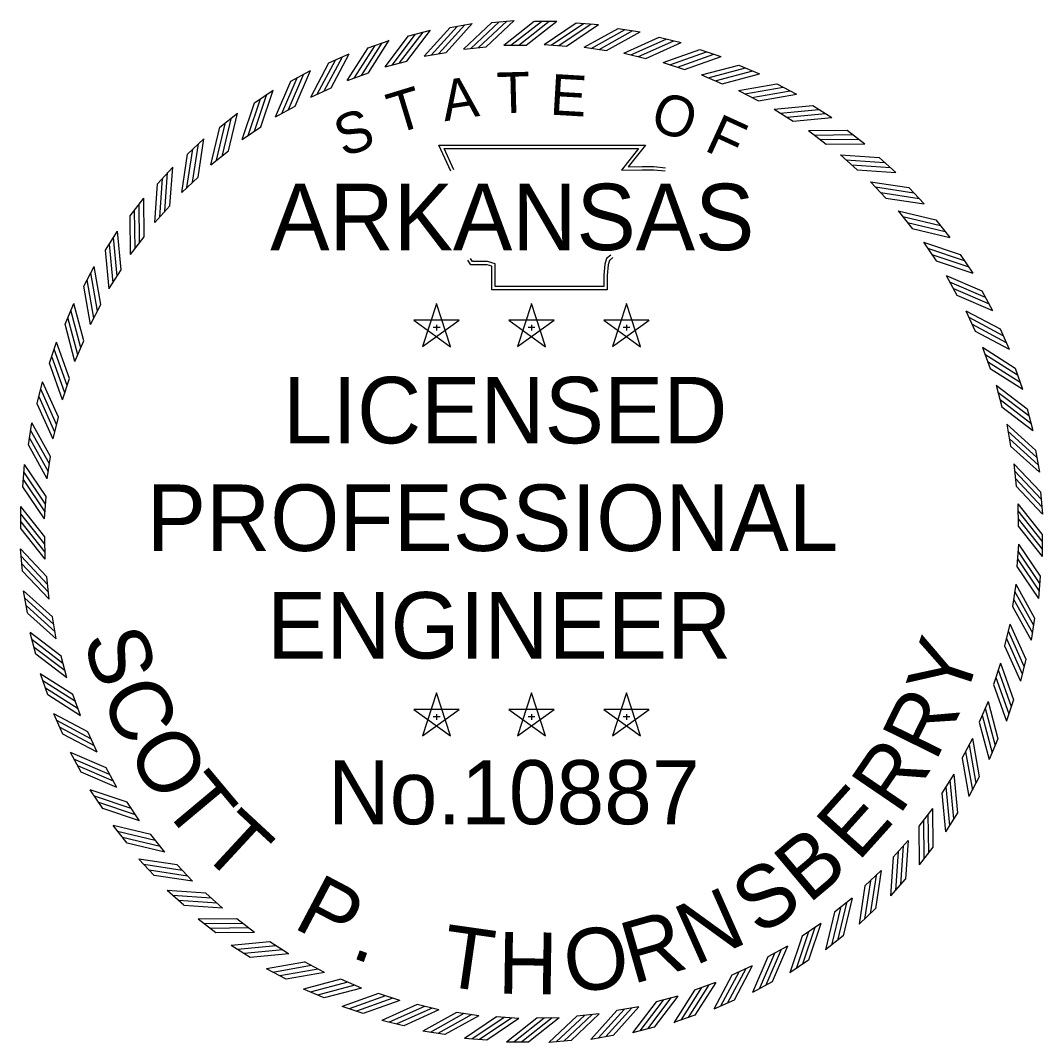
# Model space of a CAD drawing. Extents: x 185 to 5012, y 113 to 2127.
# Drawn here: x 2962.6 to 3211.1, y 185.8 to 434.2 of the extents above; entities that cross this region are included whole.
import ezdxf

# ---------------------------------------------------------------- set-up
doc = ezdxf.new("R2010")
doc.units = 0
doc.layers.add('STAMP_PP', color=7, linetype='Continuous')

msp = doc.modelspace()

# ---------------------------------------------------------------- linework, layer by layer
at = {"layer": 'STAMP_PP'}
for p, q in [((3067.05, 432.52), (3072.41, 433.46)), ((3077.23, 433.74), (3082.65, 434.24)), ((3087.54, 434.04), (3092.98, 434.04)), ((3097.73, 433.63), (3103.15, 433.23)), ((3107.9, 432.31), (3113.27, 431.47)), ((3057, 430.47), (3062.26, 431.85)), ((3117.92, 430.16), (3123.21, 428.87)), ((3047.16, 427.59), (3052.29, 429.4)), ((3070.37, 427.29), (3075.8, 427.79)), ((3080.11, 428.25), (3085.56, 428.25)), ((3089.9, 428.4), (3095.34, 428)), ((3099.66, 427.75), (3105.05, 426.9)), ((3037.58, 423.91), (3042.55, 426.14)), ((3060.74, 425.53), (3066.11, 426.48)), ((3109.34, 426.29), (3114.64, 425)), ((3127.74, 427.18), (3132.9, 425.46)), ((3051.29, 422.98), (3056.57, 424.37)), ((3118.87, 424.03), (3124.04, 422.31)), ((3137.27, 423.4), (3142.28, 421.26)), ((3028.35, 419.45), (3033.11, 422.09)), ((3042.09, 419.66), (3047.23, 421.47)), ((3128.17, 421), (3133.18, 418.85)), ((3033.19, 415.59), (3038.16, 417.82)), ((3146.46, 418.85), (3151.27, 416.31)), ((3019.51, 414.25), (3024.04, 417.27)), ((3137.19, 417.21), (3142.01, 414.66)), ((3024.65, 410.79), (3029.42, 413.43)), ((3145.87, 412.68), (3150.47, 409.74)), ((3155.25, 413.56), (3159.83, 410.62)), ((3011.13, 408.33), (3015.4, 411.71)), ((3016.54, 405.31), (3021.08, 408.34)), ((3154.15, 407.46), (3158.48, 404.15)), ((3163.56, 407.55), (3167.89, 404.25)), ((3003.27, 401.74), (3007.24, 405.46)), ((3008.91, 399.18), (3013.19, 402.57)), ((3161.97, 401.57), (3166.01, 397.91)), ((3171.36, 400.89), (3175.39, 397.24)), ((2995.98, 394.53), (2999.63, 398.56)), ((3001.82, 392.44), (3005.79, 396.17)), ((3169.27, 395.05), (3173, 391.07)), ((3178.57, 393.6), (3182.29, 389.63)), ((2989.32, 386.74), (2992.62, 391.06)), ((2995.3, 385.14), (2998.96, 389.18)), ((3176.01, 387.96), (3179.4, 383.68)), ((3185.16, 385.74), (3188.54, 381.47)), ((2983.31, 378.42), (2986.25, 383)), ((2989.41, 377.32), (2992.72, 381.66)), ((3182.14, 380.33), (3185.17, 375.79)), ((3191.08, 377.36), (3194.09, 372.83)), ((2978.02, 369.64), (2980.56, 374.44)), ((2984.19, 369.05), (2987.13, 373.64)), ((3187.62, 372.22), (3190.26, 367.45)), ((3196.28, 368.52), (3198.92, 363.76)), ((2973.47, 360.45), (2975.61, 365.45)), ((3063.76, 365.39), (3060.36, 354.95)), ((3067.15, 354.96), (3063.77, 365.4)), ((3086.84, 365.39), (3083.43, 354.95)), ((3090.23, 354.96), (3086.85, 365.4)), ((3109.92, 365.39), (3106.51, 354.95)), ((3113.31, 354.96), (3109.92, 365.4)), ((2979.66, 360.37), (2982.21, 365.19)), ((3192.41, 363.68), (3194.65, 358.71)), ((3069.25, 361.41), (3058.26, 361.42)), ((3058.27, 361.41), (3067.15, 354.94)), ((3060.37, 354.96), (3069.26, 361.4)), ((3063.77, 360.24), (3063.77, 358.86)), ((3092.33, 361.41), (3081.34, 361.42)), ((3081.35, 361.41), (3090.23, 354.94)), ((3083.45, 354.96), (3092.34, 361.4)), ((3086.85, 360.24), (3086.85, 358.86)), ((3115.4, 361.41), (3104.42, 361.42)), ((3104.43, 361.41), (3113.31, 354.94)), ((3106.53, 354.96), (3115.42, 361.4)), ((3109.93, 360.24), (3109.93, 358.86)), ((3062.98, 359.65), (3064.61, 359.65)), ((3086.06, 359.65), (3087.69, 359.65)), ((3109.13, 359.65), (3110.77, 359.65)), ((3200.74, 359.29), (3202.97, 354.32)), ((2969.69, 350.91), (2971.41, 356.07)), ((2975.87, 351.34), (2978.02, 356.36)), ((3196.48, 354.78), (3198.3, 349.64)), ((3204.42, 349.71), (3206.23, 344.58)), ((2966.71, 341.1), (2968, 346.38)), ((2972.84, 342.04), (2974.56, 347.21)), ((3199.81, 345.58), (3201.19, 340.3)), ((3207.29, 339.87), (3208.68, 334.61)), ((2964.56, 331.07), (2965.4, 336.44)), ((2970.58, 332.51), (2971.87, 337.81)), ((3202.36, 336.13), (3203.3, 330.76)), ((2969.12, 322.83), (2969.97, 328.22)), ((3209.35, 329.82), (3210.29, 324.46)), ((2963.24, 320.9), (2963.64, 326.32)), ((3204.12, 326.5), (3204.62, 321.07)), ((2968.47, 313.07), (2968.87, 318.51)), ((3210.56, 319.64), (3211.06, 314.22)), ((2962.76, 310.65), (2962.71, 316.09)), ((3205.08, 316.76), (3205.13, 311.31)), ((2968.62, 303.28), (2968.57, 308.74)), ((3210.94, 309.39), (3210.99, 303.95)), ((2963.13, 300.4), (2962.63, 305.82)), ((3205.23, 306.97), (3204.83, 301.53)), ((2969.58, 293.54), (2969.08, 298.97)), ((3210.46, 299.14), (3210.06, 293.72)), ((3204.57, 297.21), (3203.73, 291.82)), ((2964.35, 290.22), (2963.4, 295.58)), ((2971.34, 283.91), (2970.39, 289.29)), ((3209.14, 288.97), (3208.29, 283.6)), ((3203.11, 287.53), (3201.82, 282.23)), ((2966.4, 280.17), (2965.02, 285.43)), ((2973.89, 274.47), (2972.5, 279.74)), ((3206.98, 278.95), (3205.7, 273.66)), ((3200.86, 278), (3199.14, 272.83)), ((2969.28, 270.33), (2967.47, 275.46)), ((2977.21, 265.26), (2975.39, 270.4)), ((3063.76, 270.77), (3060.36, 260.33)), ((3067.15, 260.33), (3063.77, 270.78)), ((3086.84, 270.77), (3083.43, 260.33)), ((3090.23, 260.33), (3086.85, 270.78)), ((3109.92, 270.77), (3106.51, 260.33)), ((3113.31, 260.33), (3109.92, 270.78)), ((3197.83, 268.7), (3195.68, 263.68)), ((3204.01, 269.13), (3202.29, 263.97)), ((3069.25, 266.78), (3058.26, 266.79)), ((3058.27, 266.78), (3067.15, 260.32)), ((3060.37, 260.33), (3069.26, 266.78)), ((3092.33, 266.78), (3081.34, 266.79)), ((3081.35, 266.78), (3090.23, 260.32)), ((3083.45, 260.33), (3092.34, 266.78)), ((3115.4, 266.78), (3104.42, 266.79)), ((3104.43, 266.78), (3113.31, 260.32)), ((3106.53, 260.33), (3115.42, 266.78)), ((2972.96, 260.76), (2970.73, 265.72)), ((3062.98, 265.03), (3064.61, 265.03)), ((3063.77, 265.61), (3063.77, 264.24)), ((3086.06, 265.03), (3087.69, 265.03)), ((3086.85, 265.61), (3086.85, 264.24)), ((3109.13, 265.03), (3110.77, 265.03)), ((3109.93, 265.61), (3109.93, 264.24)), ((2981.28, 256.36), (2979.05, 261.33)), ((3194.04, 259.68), (3191.48, 254.86)), ((3200.23, 259.6), (3198.09, 254.59)), ((2977.42, 251.52), (2974.78, 256.28)), ((2986.08, 247.82), (2983.44, 252.6)), ((3189.51, 251), (3186.57, 246.4)), ((3195.68, 250.4), (3193.13, 245.6)), ((2982.62, 242.68), (2979.6, 247.21)), ((2991.56, 239.71), (2988.53, 244.25)), ((3184.29, 242.72), (3180.98, 238.39)), ((3190.38, 241.62), (3187.45, 237.04)), ((2988.54, 234.3), (2985.16, 238.57)), ((2997.69, 232.09), (2994.3, 236.36)), ((3178.4, 234.9), (3174.74, 230.86)), ((3184.38, 233.3), (3181.08, 228.98)), ((2995.13, 226.44), (2991.4, 230.41)), ((3004.43, 224.99), (3000.7, 228.97)), ((3171.88, 227.6), (3167.9, 223.87)), ((3177.71, 225.51), (3174.07, 221.48)), ((3002.34, 219.16), (2998.3, 222.8)), ((3011.73, 218.47), (3007.69, 222.13)), ((3164.78, 220.86), (3160.51, 217.47)), ((3170.42, 218.3), (3166.46, 214.58)), ((3010.13, 212.49), (3005.81, 215.79)), ((3019.55, 212.58), (3015.21, 215.89)), ((3157.15, 214.73), (3152.62, 211.7)), ((3162.57, 211.71), (3158.3, 208.33)), ((3018.45, 206.49), (3013.87, 209.42)), ((3027.82, 207.36), (3023.23, 210.3)), ((3149.05, 209.25), (3144.27, 206.61)), ((3027.23, 201.19), (3022.42, 203.74)), ((3036.5, 202.83), (3031.68, 205.39)), ((3140.51, 204.46), (3135.54, 202.22)), ((3154.19, 205.79), (3149.66, 202.77)), ((3036.42, 196.64), (3031.42, 198.78)), ((3045.53, 199.04), (3040.51, 201.19)), ((3131.61, 200.38), (3126.47, 198.57)), ((3145.35, 200.59), (3140.59, 197.95)), ((3054.83, 196.01), (3049.66, 197.73)), ((3122.4, 197.06), (3117.13, 195.68)), ((3045.96, 192.86), (3040.8, 194.58)), ((3064.36, 193.75), (3059.06, 195.04)), ((3112.95, 194.51), (3107.58, 193.57)), ((3136.11, 196.13), (3131.15, 193.9)), ((3074.03, 192.29), (3068.65, 193.14)), ((3083.8, 191.64), (3078.36, 192.04)), ((3093.59, 191.79), (3088.13, 191.74)), ((3103.33, 192.75), (3097.9, 192.25)), ((3126.54, 192.45), (3121.41, 190.64)), ((3055.77, 189.89), (3050.49, 191.17)), ((3116.7, 189.57), (3111.43, 188.19)), ((3065.8, 187.73), (3060.43, 188.58)), ((3075.97, 186.41), (3070.54, 186.81)), ((3106.65, 187.52), (3101.29, 186.58)), ((3086.22, 185.93), (3080.78, 185.88)), ((3096.46, 186.3), (3091.05, 185.81))]:
    msp.add_line(p, q, dxfattribs=at)
for points in [[(3060.74, 425.52), (3067.04, 432.51)], [(3062.46, 425.81), (3068.77, 432.8)], [(3064.32, 426.18), (3070.62, 433.17)], [(3066.11, 426.48), (3072.41, 433.47)], [(3070.36, 427.28), (3077.23, 433.73)], [(3072.11, 427.43), (3078.97, 433.88)], [(3073.99, 427.64), (3080.85, 434.09)], [(3075.79, 427.79), (3082.66, 434.24)], [(3080.1, 428.24), (3087.53, 434.03)], [(3081.86, 428.23), (3089.28, 434.02)], [(3083.75, 428.27), (3091.17, 434.06)], [(3085.56, 428.25), (3092.98, 434.04)], [(3089.89, 428.4), (3097.72, 433.63)], [(3091.64, 428.25), (3099.46, 433.48)], [(3093.52, 428.16), (3101.35, 433.39)], [(3095.33, 428.01), (3103.16, 433.24)], [(3099.66, 427.74), (3107.89, 432.31)], [(3051.29, 422.97), (3056.99, 430.46)], [(3052.99, 423.4), (3058.69, 430.89)], [(3054.8, 423.92), (3060.51, 431.41)], [(3056.56, 424.37), (3062.27, 431.86)], [(3101.38, 427.45), (3109.62, 432.02)], [(3103.26, 427.2), (3111.49, 431.77)], [(3105.04, 426.9), (3113.28, 431.47)], [(3109.33, 426.28), (3117.92, 430.15)], [(3042.08, 419.65), (3047.15, 427.58)], [(3043.74, 420.22), (3048.81, 428.15)], [(3045.51, 420.89), (3050.58, 428.82)], [(3047.22, 421.48), (3052.29, 429.41)], [(3111.03, 425.85), (3119.61, 429.72)], [(3112.88, 425.45), (3121.46, 429.32)], [(3114.63, 425), (3123.22, 428.87)], [(3036.49, 417.09), (3040.89, 425.42)], [(3038.15, 417.82), (3042.55, 426.15)], [(3118.86, 424.03), (3127.73, 427.18)], [(3120.51, 423.46), (3129.39, 426.61)], [(3122.32, 422.9), (3131.19, 426.05)], [(3124.03, 422.31), (3132.91, 425.46)], [(3033.18, 415.58), (3037.58, 423.9)], [(3034.79, 416.28), (3039.18, 424.61)], [(3128.16, 421), (3137.26, 423.4)], [(3129.77, 420.29), (3138.87, 422.7)], [(3026.19, 411.62), (3029.88, 420.28)], [(3027.82, 412.57), (3031.52, 421.23)], [(3029.42, 413.43), (3033.11, 422.09)], [(3131.52, 419.59), (3140.62, 421.99)], [(3133.18, 418.86), (3142.28, 421.26)], [(3024.65, 410.79), (3028.34, 419.45)], [(3137.19, 417.21), (3146.46, 418.85)], [(3138.73, 416.37), (3148, 418.02)], [(3018.01, 406.26), (3020.97, 415.2)], [(3019.56, 407.35), (3022.52, 416.28)], [(3021.07, 408.34), (3024.04, 417.27)], [(3140.42, 415.52), (3149.69, 417.17)], [(3142.01, 414.66), (3151.28, 416.31)], [(3016.54, 405.31), (3019.51, 414.24)], [(3145.87, 412.68), (3155.24, 413.56)], [(3147.33, 411.72), (3156.7, 412.6)], [(3011.75, 401.46), (3013.97, 410.61)], [(3013.18, 402.57), (3015.4, 411.72)], [(3148.95, 410.74), (3158.32, 411.61)], [(3150.46, 409.75), (3159.84, 410.62)], [(3008.91, 399.17), (3011.13, 408.32)], [(3010.29, 400.25), (3012.51, 409.4)], [(3154.14, 407.46), (3163.56, 407.55)], [(3005.79, 396.17), (3007.24, 405.47)], [(3155.52, 406.38), (3164.94, 406.48)], [(3157.05, 405.27), (3166.46, 405.37)], [(3003.1, 393.62), (3004.56, 402.92)], [(3004.45, 394.94), (3005.91, 404.24)], [(3067.26, 397.63), (3064.36, 403.91), (3114.54, 403.94), (3110.35, 398.67), (3113.76, 398.71), (3116.61, 398.75), (3119.45, 398.44)], [(3067.99, 397.96), (3065.61, 403.11), (3112.89, 403.14), (3108.69, 397.85), (3113.77, 397.92), (3116.57, 397.95), (3119.37, 397.65)], [(3158.48, 404.16), (3167.89, 404.25)], [(3001.82, 392.43), (3003.27, 401.73)], [(3161.96, 401.57), (3171.35, 400.89)], [(3163.25, 400.38), (3172.64, 399.7)], [(2998.95, 389.18), (2999.63, 398.57)], [(3164.68, 399.15), (3174.07, 398.46)], [(3166.01, 397.92), (3175.4, 397.24)], [(2996.49, 386.42), (2997.17, 395.81)], [(2997.72, 387.85), (2998.4, 397.24)], [(3169.26, 395.05), (3178.56, 393.6)], [(2995.3, 385.13), (2995.98, 394.52)], [(3170.45, 393.77), (3179.75, 392.31)], [(2992.71, 381.65), (2992.62, 391.07)], [(3171.77, 392.42), (3181.07, 390.96)], [(3173, 391.08), (3182.3, 389.63)], [(2990.49, 378.7), (2990.39, 388.11)], [(2991.6, 380.22), (2991.5, 389.64)], [(3176, 387.96), (3185.15, 385.74)], [(2989.41, 377.31), (2989.31, 386.73)], [(3177.08, 386.58), (3186.23, 384.36)], [(3178.28, 385.12), (3187.43, 382.9)], [(2987.12, 373.63), (2986.25, 383.01)], [(3179.4, 383.69), (3188.55, 381.47)], [(2986.13, 372.12), (2985.26, 381.49)], [(3182.13, 380.33), (3191.07, 377.36)], [(2984.19, 369.04), (2983.31, 378.41)], [(2985.14, 370.5), (2984.27, 379.88)], [(3183.09, 378.86), (3192.03, 375.9)], [(3106.64, 376.6), (3105.78, 375.9), (3105.5, 374.86), (3105.21, 372.26), (3105.21, 368.79), (3077.2, 368.79), (3077.2, 373.47), (3077.2, 374.51), (3076.07, 374.86), (3072.08, 374.86), (3071.37, 375.94)], [(3106.13, 377.21), (3105.08, 376.36), (3104.71, 375.01), (3104.42, 372.3), (3104.42, 369.59), (3078, 369.59), (3078, 373.47), (3078, 375.1), (3076.18, 375.66), (3072.51, 375.66), (3072.04, 376.38)], [(3184.17, 377.31), (3193.11, 374.35)], [(3185.17, 375.8), (3194.1, 372.83)], [(2981.34, 363.59), (2979.7, 372.86)], [(2982.21, 365.18), (2980.56, 374.45)], [(2980.5, 361.9), (2978.85, 371.17)], [(3187.61, 372.22), (3196.27, 368.53)], [(3188.45, 370.68), (3197.11, 366.99)], [(2979.66, 360.36), (2978.02, 369.63)], [(3189.4, 369.05), (3198.06, 365.35)], [(2978.01, 356.35), (2975.61, 365.45)], [(3190.26, 367.45), (3198.92, 363.76)], [(2977.28, 354.69), (2974.88, 363.79)], [(3192.41, 363.69), (3200.73, 359.29)], [(2975.87, 351.33), (2973.47, 360.44)], [(2976.58, 352.94), (2974.17, 362.04)], [(3193.11, 362.08), (3201.43, 357.69)], [(3193.92, 360.38), (3202.25, 355.98)], [(3194.65, 358.72), (3202.98, 354.32)], [(2974.55, 347.21), (2971.41, 356.08)], [(2973.97, 345.49), (2970.82, 354.36)], [(3196.48, 354.79), (3204.41, 349.72)], [(3197.05, 353.13), (3204.98, 348.06)], [(2972.84, 342.03), (2969.69, 350.9)], [(2973.41, 343.69), (2970.26, 352.56)], [(3197.72, 351.36), (3205.65, 346.29)], [(3198.3, 349.65), (3206.24, 344.58)], [(2971.87, 337.81), (2968, 346.39)], [(3199.8, 345.58), (3207.29, 339.87)], [(2971.42, 336.05), (2967.55, 344.63)], [(3200.23, 343.88), (3207.72, 338.18)], [(2970.59, 332.5), (2966.72, 341.09)], [(2971.02, 334.2), (2967.15, 342.78)], [(3200.75, 342.07), (3208.24, 336.36)], [(3201.2, 340.31), (3208.68, 334.6)], [(2969.97, 328.22), (2965.4, 336.45)], [(3202.35, 336.13), (3209.34, 329.83)], [(2969.67, 326.43), (2965.1, 334.66)], [(3202.64, 334.4), (3209.63, 328.1)], [(2969.13, 322.83), (2964.56, 331.06)], [(2969.41, 324.55), (2964.85, 332.79)], [(3203.01, 332.55), (3210, 326.25)], [(3203.31, 330.76), (3210.3, 324.46)], [(2968.86, 318.5), (2963.63, 326.33)], [(3204.11, 326.5), (3210.56, 319.64)], [(2968.71, 316.7), (2963.48, 324.52)], [(3204.26, 324.76), (3210.7, 317.9)], [(2968.47, 313.06), (2963.24, 320.89)], [(2968.62, 314.81), (2963.39, 322.64)], [(3204.47, 322.88), (3210.92, 316.02)], [(3204.62, 321.07), (3211.07, 314.21)], [(2968.57, 308.73), (2962.71, 316.1)], [(3205.07, 316.76), (3210.93, 309.4)], [(2968.57, 306.92), (2962.71, 314.29)], [(3205.07, 315.01), (3210.93, 307.64)], [(3205.13, 313.12), (3210.99, 305.75)], [(2968.62, 305.03), (2962.77, 312.4)], [(2968.62, 303.28), (2962.77, 310.65)], [(3205.13, 311.31), (3210.99, 303.94)], [(2969.08, 298.97), (2962.63, 305.83)], [(3205.23, 306.98), (3210.46, 299.15)], [(2969.23, 297.16), (2962.78, 304.02)], [(3204.98, 303.35), (3210.21, 295.52)], [(3205.08, 305.23), (3210.31, 297.41)], [(2969.44, 295.28), (2962.99, 302.14)], [(3204.84, 301.54), (3210.06, 293.71)], [(2969.59, 293.54), (2963.14, 300.4)], [(3204.57, 297.21), (3209.14, 288.98)], [(2970.39, 289.28), (2963.4, 295.58)], [(2970.69, 287.49), (2963.7, 293.8)], [(3204.03, 293.61), (3208.59, 285.38)], [(3204.28, 295.49), (3208.85, 287.25)], [(2971.06, 285.64), (2964.07, 291.94)], [(3203.73, 291.83), (3208.3, 283.59)], [(2971.35, 283.91), (2964.36, 290.21)], [(3202.68, 285.84), (3206.55, 277.26)], [(3203.11, 287.54), (3206.98, 278.95)], [(2972.5, 279.73), (2965.01, 285.44)], [(2972.95, 277.97), (2965.46, 283.68)], [(3202.27, 283.99), (3206.14, 275.41)], [(2973.47, 276.16), (2965.98, 281.86)], [(3201.83, 282.24), (3205.7, 273.65)], [(2973.9, 274.46), (2966.41, 280.17)], [(3200.29, 276.36), (3203.44, 267.48)], [(3200.86, 278.01), (3204, 269.14)], [(2975.39, 270.39), (2967.46, 275.46)], [(2975.98, 268.68), (2968.05, 273.75)], [(3199.73, 274.55), (3202.88, 265.68)], [(2976.65, 266.91), (2968.72, 271.98)], [(3199.14, 272.84), (3202.29, 263.96)], [(2977.22, 265.25), (2969.29, 270.32)], [(3197.82, 268.71), (3200.23, 259.6)], [(3197.12, 267.1), (3199.53, 258)], [(2979.05, 261.32), (2970.72, 265.72)], [(2979.77, 259.66), (2971.45, 264.06)], [(3195.69, 263.69), (3198.09, 254.59)], [(3196.42, 265.35), (3198.82, 256.25)], [(2980.59, 257.96), (2972.26, 262.35)], [(2981.29, 256.35), (2972.97, 260.75)], [(3194.03, 259.68), (3195.68, 250.41)], [(2983.44, 252.59), (2974.78, 256.28)], [(3192.35, 256.45), (3194, 247.18)], [(3193.2, 258.14), (3194.84, 248.87)], [(2984.3, 250.99), (2975.64, 254.69)], [(3191.49, 254.86), (3193.13, 245.59)], [(2985.25, 249.36), (2976.59, 253.05)], [(2986.08, 247.82), (2977.42, 251.51)], [(3189.51, 251), (3190.38, 241.63)], [(3188.55, 249.54), (3189.43, 240.16)], [(2988.53, 244.24), (2979.6, 247.21)], [(3186.58, 246.41), (3187.45, 237.03)], [(3187.57, 247.92), (3188.44, 238.55)], [(2989.52, 242.73), (2980.59, 245.69)], [(2990.61, 241.18), (2981.67, 244.14)], [(2991.56, 239.71), (2982.63, 242.68)], [(3183.21, 241.35), (3183.31, 231.93)], [(3184.29, 242.73), (3184.38, 233.31)], [(2994.3, 236.35), (2985.15, 238.57)], [(3182.1, 239.82), (3182.19, 230.4)], [(2995.41, 234.92), (2986.26, 237.14)], [(3180.98, 238.39), (3181.08, 228.97)], [(2996.62, 233.47), (2987.47, 235.68)], [(2997.7, 232.08), (2988.55, 234.3)], [(3177.21, 233.62), (3176.53, 224.23)], [(3178.4, 234.91), (3177.72, 225.52)], [(3175.97, 232.19), (3175.29, 222.8)], [(3000.7, 228.96), (2991.4, 230.41)], [(3001.93, 227.63), (2992.63, 229.08)], [(3174.75, 230.86), (3174.07, 221.47)], [(3003.25, 226.28), (2993.95, 227.73)], [(3004.44, 224.99), (2995.14, 226.44)], [(3170.59, 226.42), (3169.14, 217.12)], [(3171.88, 227.61), (3170.43, 218.31)], [(3167.91, 223.87), (3166.46, 214.57)], [(3169.24, 225.1), (3167.79, 215.8)], [(3007.69, 222.12), (2998.3, 222.8)], [(3009.02, 220.89), (2999.63, 221.58)], [(3010.45, 219.66), (3001.06, 220.34)], [(3011.74, 218.47), (3002.35, 219.15)], [(3163.4, 219.79), (3161.19, 210.64)], [(3164.79, 220.87), (3162.57, 211.72)], [(3160.52, 217.47), (3158.3, 208.32)], [(3161.95, 218.58), (3159.73, 209.44)], [(3015.22, 215.89), (3005.8, 215.79)], [(3016.65, 214.77), (3007.23, 214.68)], [(3018.17, 213.66), (3008.76, 213.56)], [(3155.69, 213.78), (3152.73, 204.84)], [(3157.16, 214.74), (3154.19, 205.8)], [(3019.56, 212.58), (3010.14, 212.49)], [(3152.62, 211.7), (3149.66, 202.77)], [(3154.14, 212.69), (3151.18, 203.76)], [(3023.23, 210.29), (3013.86, 209.42)], [(3024.75, 209.3), (3015.38, 208.43)], [(3149.05, 209.26), (3145.36, 200.6)], [(3026.37, 208.32), (3016.99, 207.44)], [(3027.83, 207.36), (3018.46, 206.49)], [(3144.28, 206.61), (3140.59, 197.95)], [(3145.88, 207.47), (3142.18, 198.81)], [(3147.51, 208.42), (3143.82, 199.76)], [(3031.69, 205.38), (3022.42, 203.73)], [(3033.28, 204.52), (3024.01, 202.87)], [(3138.91, 203.76), (3134.52, 195.43)], [(3140.52, 204.46), (3136.12, 196.14)], [(3034.97, 203.67), (3025.7, 202.02)], [(3036.51, 202.84), (3027.24, 201.19)], [(3135.55, 202.22), (3131.15, 193.89)], [(3137.21, 202.95), (3132.81, 194.62)], [(3040.52, 201.18), (3031.42, 198.78)], [(3042.18, 200.45), (3033.08, 198.05)], [(3043.93, 199.75), (3034.83, 197.34)], [(3045.53, 199.04), (3036.43, 196.64)], [(3128.19, 199.15), (3123.12, 191.22)], [(3129.96, 199.82), (3124.89, 191.89)], [(3131.62, 200.39), (3126.55, 192.46)], [(3049.66, 197.73), (3040.79, 194.58)], [(3051.38, 197.14), (3042.51, 193.99)], [(3053.18, 196.58), (3044.31, 193.43)], [(3120.71, 196.64), (3115.01, 189.15)], [(3122.41, 197.07), (3116.7, 189.58)], [(3126.48, 198.57), (3121.41, 190.63)], [(3054.84, 196.01), (3045.97, 192.86)], [(3059.06, 195.04), (3050.48, 191.17)], [(3060.82, 194.59), (3052.24, 190.73)], [(3062.67, 194.19), (3054.08, 190.32)], [(3109.38, 193.86), (3103.07, 186.87)], [(3111.23, 194.23), (3104.93, 187.24)], [(3112.96, 194.52), (3106.66, 187.53)], [(3117.14, 195.67), (3111.43, 188.19)], [(3118.89, 196.12), (3113.19, 188.63)], [(3064.36, 193.76), (3055.78, 189.89)], [(3068.65, 193.14), (3060.42, 188.57)], [(3070.44, 192.84), (3062.21, 188.27)], [(3072.31, 192.59), (3064.08, 188.02)], [(3074.04, 192.3), (3065.81, 187.73)], [(3078.37, 192.03), (3070.54, 186.81)], [(3080.17, 191.88), (3072.35, 186.66)], [(3082.06, 191.79), (3074.23, 186.56)], [(3083.81, 191.64), (3075.98, 186.41)], [(3088.14, 191.74), (3080.77, 185.88)], [(3089.95, 191.74), (3082.58, 185.88)], [(3091.84, 191.8), (3084.47, 185.94)], [(3093.59, 191.8), (3086.22, 185.94)], [(3097.9, 192.25), (3091.04, 185.8)], [(3099.71, 192.4), (3092.85, 185.95)], [(3101.59, 192.61), (3094.73, 186.17)], [(3103.33, 192.76), (3096.47, 186.31)], [(3107.59, 193.56), (3101.29, 186.57)]]:
    msp.add_lwpolyline(points, dxfattribs=at)

# ---------------------------------------------------------------- texts
for s, height, rotation, p in [('A', 9.9, 8.6788, (3065.73, 409.71)), ('T', 9.9, 1.4789, (3078.52, 411.67)), ('E', 9.9, 356.672, (3091.18, 411.37)), ('T', 9.9, 16.9015, (3053.72, 406.57)), ('O', 9.9, 341.2218, (3115.22, 407.98)), ('S', 9.9, 19.7726, (3041.13, 400.92)), ('F', 9.9, 335.3628, (3128.56, 402.76)), ('S', 15.03, 286.9475, (2977.74, 284.08)), ('Y', 15.03, 71.7733, (3191.93, 268.04)), ('C', 15.03, 294.2435, (2981.92, 270.37)), ('R', 15.03, 63.7477, (3185.05, 253.85)), ('O', 15.03, 301.9044, (2988.15, 256.66)), ('R', 15.03, 55.7221, (3176.25, 240.77)), ('T', 15.03, 309.93, (2996.56, 243.33)), ('E', 15.03, 48.0613, (3166.23, 229.54)), ('T', 15.03, 317.226, (3005.77, 232.34)), ('B', 15.03, 40.0357, (3154.22, 219.32)), ('S', 15.03, 32.7397, (3142.16, 211.56)), ('P', 15.03, 332.1828, (3028.58, 213.9)), ('N', 15.03, 23.9845, (3126.54, 204.37)), ('R', 15.03, 15.9589, (3111.41, 199.94)), ('T', 15.03, 351.882, (3064.41, 199.71)), ('O', 15.03, 7.9332, (3095.8, 197.66)), ('H', 15.03, 359.178, (3078.61, 197.69)), ('.', 15.03, 340.2084, (3042.57, 206.64))]:
    msp.add_text(s, height=height, rotation=rotation, dxfattribs=at).set_placement(p)
for s, height, p in [('ARKANSAS', 16.155, (3023.35, 378.4)), ('LICENSED', 16.155, (3026.42, 331.45)), ('PROFESSIONAL', 16.1547, (2993.34, 305.29)), ('ENGINEER', 16.155, (3022.58, 279.14)), ('No.10887', 15.578, (3037.34, 238.86))]:
    msp.add_text(s, height=height, dxfattribs=at).set_placement(p)

doc.saveas('drawing.dxf')
